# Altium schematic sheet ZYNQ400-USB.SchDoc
size A3
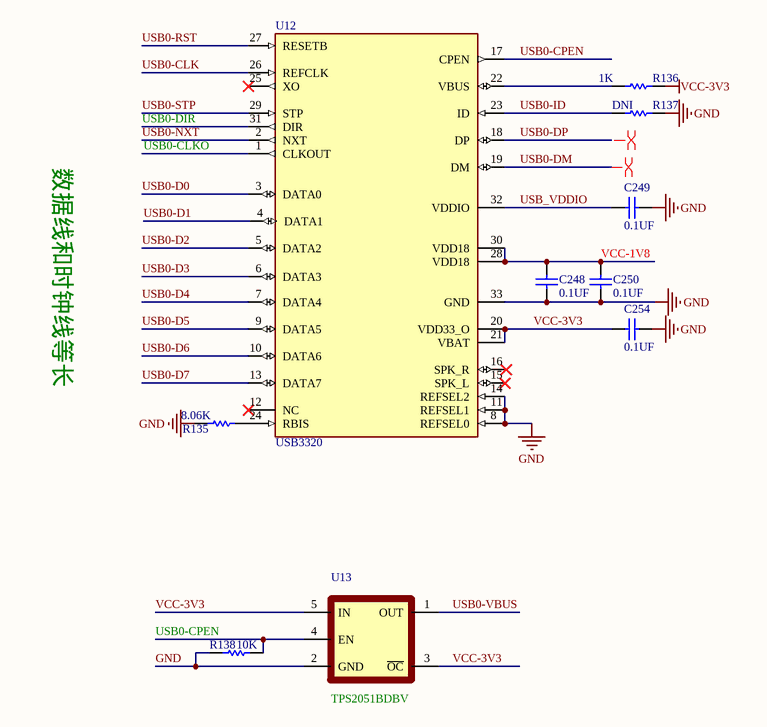
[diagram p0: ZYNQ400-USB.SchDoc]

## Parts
C248  0.1UF  [0402]
C249  0.1UF  [0402]
C250  0.1UF  [0402]
C254  0.1UF  [0402]
R135  8.06K  [0402]
R136  1K  [0402]
R137  DNI  [0402]
R138  10K  [0402]
U12  USB3320  [QFN32]
U13  TPS2051BDBV  [SOT23-5]

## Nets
GND: C248.1 C249.1 C250.1 C254.2 R135.1 R137.2 R138.2 U12.8(REFSEL0) U12.11(REFSEL1) U12.14(REFSEL2) U12.33(GND) U13.2(GND)
VCC-3V3: C254.1 R136.2 U12.20(VDD33_O) U12.21(VBAT) U13.3(~{OC}) U13.5(IN)
USB0-CLK: U12.26(REFCLK)
USB0-CLKO: U12.1(CLKOUT)
USB0-CPEN: R138.1 U12.17(CPEN) U13.4(EN)
USB0-D0: U12.3(DATA0)
USB0-D1: U12.4(DATA1)
USB0-D2: U12.5(DATA2)
USB0-D3: U12.6(DATA3)
USB0-D4: U12.7(DATA4)
USB0-D5: U12.9(DATA5)
USB0-D6: U12.10(DATA6)
USB0-D7: U12.13(DATA7)
USB0-DIR: U12.31(DIR)
USB0-DM: U12.19(DM)
USB0-DP: U12.18(DP)
USB0-ID: R137.1 U12.23(ID)
USB0-NXT: U12.2(NXT)
USB0-RST: U12.27(RESETB)
USB0-STP: U12.29(STP)
USB0-VBUS: U13.1(OUT)
USB_VDDIO: C249.2 U12.32(VDDIO)
VCC-1V8: C248.2 C250.2 U12.28(VDD18) U12.30(VDD18)
NetR135_2: R135.2 U12.24(RBIS)
NetR136_1: R136.1 U12.22(VBUS)

Not connected (* = marked no-connect by the designer): U12 12(NC)* 15(SPK_L)* 16(SPK_R) 25(XO)*

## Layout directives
differential pair: (no net found under the mark), USB0-DM

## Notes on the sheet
- 数据线和时钟线等长

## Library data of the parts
C248-C250 C254 = Cap: Capacitor
R135 R136 R138 = Res1: Resistor
R137 = Res1: Resistor; Value: 4K7
U12 = USB3320C-EZK
U13 = TPS2051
